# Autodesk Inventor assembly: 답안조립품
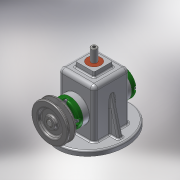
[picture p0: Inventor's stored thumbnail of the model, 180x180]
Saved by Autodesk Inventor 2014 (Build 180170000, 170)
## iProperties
Created: 2017-07
Part Number: 답안조립품
Document SubType Name: Assembly
Designer: user
Author: user
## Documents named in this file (16)
- C:\Users\user\Desktop\470708V1015\답안조립품.iam
- C:\Users\user\Desktop\470708V1015\V벨트풀리.ipt
- C:\Users\user\Desktop\470708V1015\고정핀 1.2 x  8.ipt
- C:\Users\user\Desktop\470708V1015\뒤커버.ipt
- C:\Users\user\Desktop\470708V1015\링크.ipt
- C:\Users\user\Desktop\470708V1015\멈춤나사 M3x8.ipt
- C:\Users\user\Desktop\470708V1015\베어링 12 x 32 x 10.ipt
- C:\Users\user\Desktop\470708V1015\본체.ipt
- C:\Users\user\Desktop\470708V1015\볼트 M4 x 12.ipt
- C:\Users\user\Desktop\470708V1015\부시.ipt
- C:\Users\user\Desktop\470708V1015\슬라이드.ipt
- C:\Users\user\Desktop\470708V1015\앞커버.ipt
- C:\Users\user\Desktop\470708V1015\오일실 12 25 7.ipt
- C:\Users\user\Desktop\470708V1015\키 4 x 4 x 10.ipt
- C:\Users\user\Desktop\470708V1015\편심축.ipt
- C:\Users\user\Desktop\470708V1015\핀 5 x 18.ipt
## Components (3 placed, 3 different names)
1. V벨트풀리:1
2. 고정핀 1.2 x  8:1
3. 핀 5 x 18:1 — 각도:3
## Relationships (1: Angle 1)
- 각도:3 [Angle]: 핀 5 x 18:1
